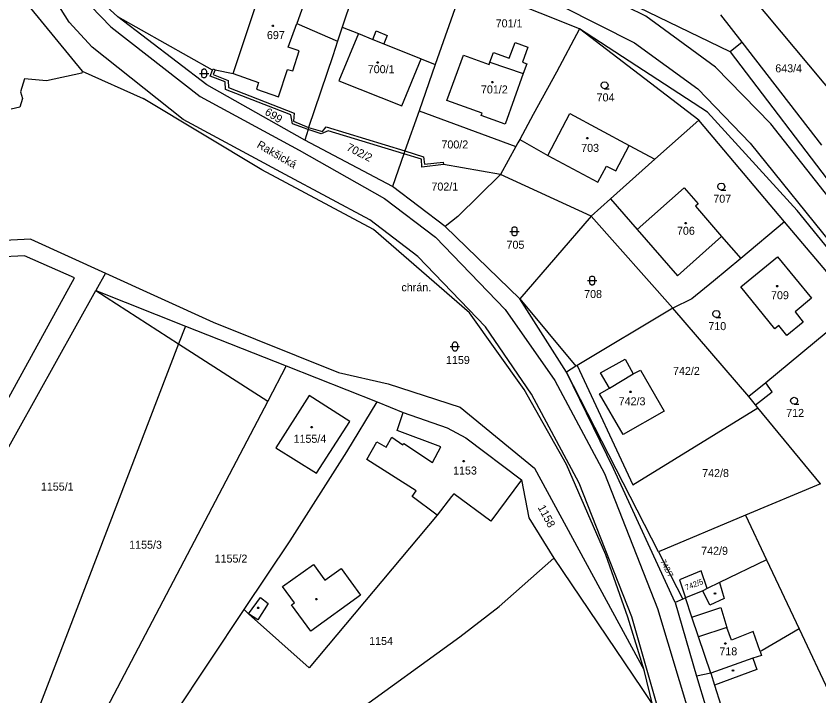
# Model space of a CAD drawing. Extents: x -621797 to -620972, y -1175539 to -1174697.
# Drawn here: x -621483.9 to -621313.4, y -1175130.5 to -1174986.3 of the extents above; entities that cross this region are included whole.
import ezdxf

# ---------------------------------------------------------------- set-up
doc = ezdxf.new("R2010")
doc.units = 0
for name, color, linetype in [('INZ mimo EON - nadz', 7, 'Continuous'), ('Rozvod plynu EON', 7, 'Continuous'), ('SDEL EON', 7, 'Continuous'), ('SDEL EON - popis', 7, 'Continuous'), ('Silnoproud EON', 7, 'Continuous'), ('Silnoproud EON - popis', 7, 'Continuous')]:
    doc.layers.add(name, color=color, linetype=linetype)

msp = doc.modelspace()

# ---------------------------------------------------------------- linework, layer by layer
at = {"layer": 'Rozvod plynu EON'}
for points in [[(-621429.27, -1174988.2), (-621429.18, -1174988.35), (-621429.27, -1174988.5), (-621429.45, -1174988.5), (-621429.54, -1174988.35), (-621429.45, -1174988.2)], [(-621407.03, -1174995.96), (-621406.94, -1174996.11), (-621407.03, -1174996.26), (-621407.21, -1174996.26), (-621407.3, -1174996.11), (-621407.21, -1174995.96)], [(-621382.65, -1175000.18), (-621382.56, -1175000.33), (-621382.65, -1175000.48), (-621382.83, -1175000.48), (-621382.92, -1175000.33), (-621382.83, -1175000.18)], [(-621362.5, -1175012.02), (-621362.41, -1175012.17), (-621362.5, -1175012.32), (-621362.68, -1175012.32), (-621362.77, -1175012.17), (-621362.68, -1175012.02)], [(-621341.64, -1175030.06), (-621341.55, -1175030.21), (-621341.64, -1175030.36), (-621341.82, -1175030.36), (-621341.91, -1175030.21), (-621341.82, -1175030.06)], [(-621322.2, -1175043.44), (-621322.11, -1175043.59), (-621322.2, -1175043.74), (-621322.38, -1175043.74), (-621322.47, -1175043.59), (-621322.38, -1175043.44)], [(-621353.34, -1175065.85), (-621353.25, -1175066), (-621353.34, -1175066.15), (-621353.52, -1175066.15), (-621353.61, -1175066), (-621353.52, -1175065.85)], [(-621421.04, -1175073.36), (-621420.95, -1175073.51), (-621421.04, -1175073.66), (-621421.22, -1175073.66), (-621421.31, -1175073.51), (-621421.22, -1175073.36)], [(-621388.77, -1175080.59), (-621388.68, -1175080.74), (-621388.77, -1175080.89), (-621388.95, -1175080.89), (-621389.04, -1175080.74), (-621388.95, -1175080.59)], [(-621335.38, -1175108.68), (-621335.29, -1175108.83), (-621335.38, -1175108.98), (-621335.56, -1175108.98), (-621335.65, -1175108.83), (-621335.56, -1175108.68)], [(-621420.01, -1175109.87), (-621419.92, -1175110.02), (-621420.01, -1175110.17), (-621420.19, -1175110.17), (-621420.28, -1175110.02), (-621420.19, -1175109.87)], [(-621432.39, -1175111.69), (-621432.3, -1175111.84), (-621432.39, -1175111.99), (-621432.57, -1175111.99), (-621432.66, -1175111.84), (-621432.57, -1175111.69)], [(-621333.19, -1175119.25), (-621333.1, -1175119.4), (-621333.19, -1175119.55), (-621333.37, -1175119.55), (-621333.46, -1175119.4), (-621333.37, -1175119.25)], [(-621331.58, -1175124.97), (-621331.49, -1175125.12), (-621331.58, -1175125.27), (-621331.76, -1175125.27), (-621331.85, -1175125.12), (-621331.76, -1175124.97)]]:
    msp.add_lwpolyline(points, close=True, dxfattribs=at)
at = {"layer": 'SDEL EON'}
for points in [[(-621444.47, -1174997.95), (-621444.37, -1174997.66), (-621444.12, -1174997.48), (-621443.81, -1174997.48), (-621443.56, -1174997.66), (-621443.46, -1174997.95), (-621443.46, -1174998.95), (-621443.56, -1174999.24), (-621443.81, -1174999.42), (-621444.12, -1174999.42), (-621444.37, -1174999.24), (-621444.47, -1174998.95)], [(-621378.56, -1175031.46), (-621378.46, -1175031.17), (-621378.21, -1175030.99), (-621377.9, -1175030.99), (-621377.65, -1175031.17), (-621377.55, -1175031.46), (-621377.55, -1175032.46), (-621377.65, -1175032.75), (-621377.9, -1175032.93), (-621378.21, -1175032.93), (-621378.46, -1175032.75), (-621378.56, -1175032.46)], [(-621362.08, -1175041.91), (-621361.98, -1175041.62), (-621361.73, -1175041.44), (-621361.42, -1175041.44), (-621361.17, -1175041.62), (-621361.07, -1175041.91), (-621361.07, -1175042.91), (-621361.17, -1175043.2), (-621361.42, -1175043.38), (-621361.73, -1175043.38), (-621361.98, -1175043.2), (-621362.08, -1175042.91)], [(-621391.2, -1175055.91), (-621391.1, -1175055.62), (-621390.85, -1175055.44), (-621390.54, -1175055.44), (-621390.29, -1175055.62), (-621390.19, -1175055.91), (-621390.19, -1175056.91), (-621390.29, -1175057.2), (-621390.54, -1175057.38), (-621390.85, -1175057.38), (-621391.1, -1175057.2), (-621391.2, -1175056.91)]]:
    msp.add_lwpolyline(points, close=True, dxfattribs=at)
for points in [[(-621444.97, -1174998.45), (-621443.7, -1174998.45), (-621442.97, -1174998.45)], [(-621358.93, -1175001.69), (-621359.31, -1175001.59), (-621359.58, -1175001.32), (-621359.68, -1175000.95), (-621359.58, -1175000.58), (-621359.31, -1175000.31), (-621358.94, -1175000.21), (-621358.57, -1175000.31), (-621358.3, -1175000.58), (-621358.2, -1175000.96), (-621358.3, -1175001.34), (-621358.57, -1175001.61), (-621358.95, -1175001.71), (-621357.95, -1175001.71)], [(-621334.15, -1175023.19), (-621334.53, -1175023.09), (-621334.8, -1175022.82), (-621334.9, -1175022.45), (-621334.8, -1175022.08), (-621334.53, -1175021.81), (-621334.16, -1175021.71), (-621333.79, -1175021.81), (-621333.52, -1175022.08), (-621333.42, -1175022.46), (-621333.52, -1175022.84), (-621333.79, -1175023.11), (-621334.17, -1175023.21), (-621333.17, -1175023.21)], [(-621379.06, -1175031.96), (-621377.79, -1175031.96), (-621377.06, -1175031.96)], [(-621362.58, -1175042.41), (-621361.31, -1175042.41), (-621360.58, -1175042.41)], [(-621335.21, -1175050.22), (-621335.59, -1175050.12), (-621335.86, -1175049.85), (-621335.96, -1175049.48), (-621335.86, -1175049.11), (-621335.59, -1175048.84), (-621335.22, -1175048.74), (-621334.85, -1175048.84), (-621334.58, -1175049.11), (-621334.48, -1175049.49), (-621334.58, -1175049.87), (-621334.85, -1175050.14), (-621335.23, -1175050.24), (-621334.23, -1175050.24)], [(-621391.7, -1175056.41), (-621390.43, -1175056.41), (-621389.7, -1175056.41)], [(-621318.68, -1175068.64), (-621319.06, -1175068.54), (-621319.33, -1175068.27), (-621319.43, -1175067.9), (-621319.33, -1175067.53), (-621319.06, -1175067.26), (-621318.69, -1175067.16), (-621318.32, -1175067.26), (-621318.05, -1175067.53), (-621317.95, -1175067.91), (-621318.05, -1175068.29), (-621318.32, -1175068.56), (-621318.7, -1175068.66), (-621317.7, -1175068.66)]]:
    msp.add_lwpolyline(points, dxfattribs=at)
at = {"layer": 'SDEL EON - popis'}
for p, q in [((-621350.15, -1174986.32), (-621364.76, -1174979.08)), ((-621472.58, -1174987.57), (-621475.19, -1174983.54)), ((-621468.04, -1174984.21), (-621463.78, -1174988.57)), ((-621368.03, -1174984.17), (-621352.56, -1174991.96)), ((-621467.72, -1174992.88), (-621472.58, -1174987.57)), ((-621426.08, -1174992.85), (-621424.29, -1174987.85)), ((-621335.41, -1174997.12), (-621350.15, -1174986.32)), ((-621463.78, -1174988.57), (-621444.82, -1175003.37)), ((-621411.18, -1174990.01), (-621415.34, -1174999.99)), ((-621408.17, -1174991.22), (-621405.81, -1174992.17)), ((-621448.44, -1175008.26), (-621467.72, -1174992.88)), ((-621423.77, -1174993.68), (-621426.08, -1174992.85)), ((-621352.56, -1174991.96), (-621339.11, -1175001.74)), ((-621425.15, -1174997.93), (-621423.77, -1174993.68)), ((-621402, -1175005.34), (-621397.86, -1174995.37)), ((-621383.26, -1174996.06), (-621376.19, -1174998.49)), ((-621441.59, -1174997.7), (-621442.03, -1174998.7)), ((-621428.16, -1175003.44), (-621426.24, -1174997.59)), ((-621426.24, -1174997.59), (-621425.15, -1174997.93)), ((-621323.62, -1175009.12), (-621335.41, -1174997.12)), ((-621442.03, -1174998.7), (-621438.86, -1174999.94)), ((-621437.78, -1174998.47), (-621432.38, -1175000.41)), ((-621438.86, -1174999.94), (-621438.76, -1175001.46)), ((-621438.76, -1175001.46), (-621424.83, -1175006.86)), ((-621432.38, -1175000.41), (-621432.86, -1175001.82)), ((-621415.34, -1174999.99), (-621402, -1175005.34)), ((-621432.86, -1175001.82), (-621428.16, -1175003.44)), ((-621339.11, -1175001.74), (-621328.01, -1175013.22)), ((-621444.82, -1175003.37), (-621423.78, -1175014.7)), ((-621426.75, -1175019.91), (-621448.44, -1175008.26)), ((-621424.83, -1175006.86), (-621424.97, -1175008.6)), ((-621424.97, -1175008.6), (-621421.81, -1175009.93)), ((-621421.81, -1175009.93), (-621418.81, -1175010.74)), ((-621418.81, -1175010.74), (-621418.01, -1175009.8)), ((-621418.01, -1175009.8), (-621401.31, -1175014.91)), ((-621282.85, -1175060.98), (-621323.62, -1175009.12)), ((-621328.01, -1175013.22), (-621287.02, -1175064.24)), ((-621423.78, -1175014.7), (-621405.63, -1175025)), ((-621401.31, -1175014.91), (-621397.36, -1175016.12)), ((-621356.52, -1175019.14), (-621353.7, -1175013.73)), ((-621397.36, -1175016.12), (-621397.16, -1175017.74)), ((-621370.99, -1175015.9), (-621360.4, -1175021.51)), ((-621397.16, -1175017.74), (-621393.22, -1175017.3)), ((-621393.22, -1175017.3), (-621393.11, -1175017.81)), ((-621360.4, -1175021.51), (-621358.54, -1175018.11)), ((-621358.54, -1175018.11), (-621356.52, -1175019.14)), ((-621408.77, -1175029.49), (-621426.75, -1175019.91)), ((-621405.63, -1175025), (-621394.86, -1175033.18)), ((-621398.61, -1175037.31), (-621408.77, -1175029.49)), ((-621352.01, -1175031.59), (-621343.43, -1175041.38)), ((-621394.86, -1175033.18), (-621380.01, -1175048.54)), ((-621343.43, -1175041.38), (-621334.08, -1175033.04)), ((-621384.23, -1175052.21), (-621398.61, -1175037.31)), ((-621466.98, -1175044.53), (-621449.39, -1175055.82)), ((-621376.96, -1175046.31), (-621365.06, -1175060.59)), ((-621380.01, -1175048.54), (-621369.49, -1175063.63)), ((-621374.45, -1175066.49), (-621384.23, -1175052.21)), ((-621449.39, -1175055.82), (-621430.45, -1175067.98)), ((-621357.86, -1175065.27), (-621352.83, -1175062.22)), ((-621369.49, -1175063.63), (-621358.94, -1175083.35)), ((-621323.34, -1175066.01), (-621324.69, -1175064.07)), ((-621326.9, -1175068.78), (-621323.34, -1175066.01)), ((-621364.3, -1175085.37), (-621374.45, -1175066.49)), ((-621403, -1175074.21), (-621401.72, -1175070.37)), ((-621393.73, -1175077.67), (-621403, -1175074.21)), ((-621405.28, -1175077.74), (-621404.1, -1175075.63)), ((-621404.1, -1175075.63), (-621401.74, -1175077.27)), ((-621409.38, -1175080.36), (-621407.29, -1175076.62)), ((-621407.29, -1175076.62), (-621405.28, -1175077.74)), ((-621401.74, -1175077.27), (-621401.54, -1175077)), ((-621401.54, -1175077), (-621395.46, -1175081.03)), ((-621395.46, -1175081.03), (-621393.73, -1175077.67)), ((-621398.93, -1175087), (-621409.38, -1175080.36)), ((-621358.94, -1175083.35), (-621347.7, -1175112.01)), ((-621353.17, -1175113.73), (-621364.3, -1175085.37)), ((-621399.8, -1175088.22), (-621398.93, -1175087)), ((-621394.5, -1175092.17), (-621399.8, -1175088.22)), ((-621427.31, -1175107.32), (-621420.76, -1175102.68)), ((-621420.76, -1175102.68), (-621418.34, -1175105.98)), ((-621418.34, -1175105.98), (-621414.84, -1175103.48)), ((-621414.84, -1175103.48), (-621410.72, -1175109.19)), ((-621334.51, -1175106.45), (-621333.56, -1175109.87)), ((-621424.78, -1175110.77), (-621427.31, -1175107.32)), ((-621336.62, -1175111.31), (-621338.08, -1175108.26)), ((-621434.56, -1175113.09), (-621431.97, -1175109.65)), ((-621431.97, -1175109.65), (-621430.34, -1175110.95)), ((-621410.72, -1175109.19), (-621421.29, -1175116.83)), ((-621340.39, -1175113.82), (-621341.75, -1175109.71)), ((-621333.56, -1175109.87), (-621336.62, -1175111.31)), ((-621430.34, -1175110.95), (-621432.56, -1175114.38)), ((-621425.37, -1175111.2), (-621424.78, -1175110.77)), ((-621421.29, -1175116.83), (-621425.37, -1175111.2)), ((-621347.7, -1175112.01), (-621340.8, -1175134.9)), ((-621340.39, -1175113.82), (-621334.24, -1175111.78)), ((-621334.24, -1175111.78), (-621332.97, -1175116.04)), ((-621432.56, -1175114.38), (-621434.56, -1175113.09)), ((-621346.63, -1175136.41), (-621353.17, -1175113.73)), ((-621339, -1175118.01), (-621340.39, -1175113.82)), ((-621332.97, -1175116.04), (-621339, -1175118.01)), ((-621331.99, -1175118.72), (-621332.97, -1175116.04)), ((-621327.42, -1175116.9), (-621331.99, -1175118.72)), ((-621325.93, -1175121.13), (-621327.42, -1175116.9)), ((-621336.39, -1175125.7), (-621339, -1175118.01)), ((-621327.46, -1175122.56), (-621326.59, -1175124.96)), ((-621336.39, -1175125.7), (-621335.58, -1175128.26)), ((-621326.59, -1175124.96), (-621335.58, -1175128.26)), ((-621335.58, -1175128.26), (-621334.24, -1175132.49))]:
    msp.add_line(p, q, dxfattribs=at)
at = {"layer": 'Silnoproud EON'}
for p, q in [((-621408.78, -1174971.11), (-621414.62, -1174988.62)), ((-621437.78, -1174998.47), (-621431.19, -1174978.52)), ((-621388.75, -1174979.17), (-621394.87, -1174996.57)), ((-621364.26, -1174989.02), (-621388.75, -1174979.17)), ((-621332.26, -1174993.86), (-621360.13, -1174980.38)), ((-621462.25, -1174986.43), (-621466.27, -1174982.79)), ((-621422.1, -1174981.75), (-621424.29, -1174987.85)), ((-621305.54, -1175008.66), (-621327.66, -1174982.17)), ((-621480.81, -1174984.62), (-621469.86, -1174997.98)), ((-621329.73, -1174991.82), (-621334.24, -1174986.03)), ((-621442.16, -1174997.77), (-621462.25, -1174986.43)), ((-621443.35, -1175000.86), (-621462.25, -1174986.43)), ((-621424.29, -1174987.85), (-621415.61, -1174991.58)), ((-621414.62, -1174988.62), (-621415.61, -1174991.58)), ((-621414.62, -1174988.62), (-621411.18, -1174990.01)), ((-621408.17, -1174991.22), (-621407.46, -1174989.44)), ((-621407.46, -1174989.44), (-621405.09, -1174990.39)), ((-621364.26, -1174989.02), (-621369.14, -1174998.17)), ((-621337.06, -1175006.7), (-621364.26, -1174989.02)), ((-621338.95, -1175008.36), (-621364.26, -1174989.02)), ((-621411.18, -1174990.01), (-621408.17, -1174991.22)), ((-621405.09, -1174990.39), (-621405.81, -1174992.17)), ((-621415.61, -1174991.58), (-621416.66, -1174994.72)), ((-621405.81, -1174992.17), (-621397.86, -1174995.37)), ((-621379.17, -1174995.2), (-621377.95, -1174991.86)), ((-621377.95, -1174991.86), (-621375.23, -1174992.86)), ((-621375.23, -1174992.86), (-621376.38, -1174996.08)), ((-621329.73, -1174991.82), (-621332.26, -1174993.86)), ((-621312.83, -1175013.67), (-621329.73, -1174991.82)), ((-621416.66, -1174994.72), (-621421.81, -1175009.93)), ((-621392.39, -1175004.19), (-621388.92, -1174994.58)), ((-621388.92, -1174994.58), (-621383.45, -1174996.57)), ((-621383.26, -1174996.06), (-621382.5, -1174993.98)), ((-621382.5, -1174993.98), (-621379.17, -1174995.2)), ((-621332.26, -1174993.86), (-621281.81, -1175060.17)), ((-621397.86, -1174995.37), (-621394.87, -1174996.57)), ((-621383.45, -1174996.57), (-621383.26, -1174996.06)), ((-621376.38, -1174996.08), (-621375.44, -1174996.42)), ((-621375.44, -1174996.42), (-621376.19, -1174998.49)), ((-621469.86, -1174997.98), (-621469.95, -1174998.37)), ((-621469.86, -1174997.98), (-621456.9, -1175003.74)), ((-621442.7, -1174999.06), (-621442.16, -1174997.77)), ((-621442.16, -1174997.77), (-621442.05, -1174997.49)), ((-621442.05, -1174997.49), (-621441.59, -1174997.7)), ((-621441.59, -1174997.7), (-621437.78, -1174998.47)), ((-621394.87, -1174996.57), (-621398.31, -1175006.37)), ((-621369.14, -1174998.17), (-621374.08, -1175007.2)), ((-621482.1, -1174999.58), (-621482.97, -1175002.34)), ((-621477.45, -1175000.01), (-621482.1, -1174999.58)), ((-621469.95, -1174998.37), (-621477.45, -1175000.01)), ((-621439.51, -1175000.25), (-621442.7, -1174999.06)), ((-621376.19, -1174998.49), (-621380.06, -1175009.23)), ((-621422.6, -1175012.62), (-621443.35, -1175000.86)), ((-621439.44, -1175001.88), (-621439.51, -1175000.25)), ((-621482.97, -1175002.34), (-621482.49, -1175003.74)), ((-621425.56, -1175007.21), (-621439.44, -1175001.88)), ((-621482.49, -1175003.74), (-621483.1, -1175005.58)), ((-621431.69, -1175018.92), (-621456.9, -1175003.74)), ((-621384.91, -1175006.89), (-621392.39, -1175004.19)), ((-621483.1, -1175005.58), (-621484.9, -1175006.03)), ((-621398.31, -1175006.37), (-621401.31, -1175014.91)), ((-621398.31, -1175006.37), (-621377.79, -1175013.96)), ((-621318.03, -1175027.56), (-621337.06, -1175006.7)), ((-621425.17, -1175009.18), (-621425.56, -1175007.21)), ((-621385.1, -1175007.41), (-621384.91, -1175006.89)), ((-621380.06, -1175009.23), (-621385.1, -1175007.41)), ((-621374.08, -1175007.2), (-621376.96, -1175012.46)), ((-621370.99, -1175015.9), (-621366.3, -1175006.92)), ((-621366.3, -1175006.92), (-621353.7, -1175013.73)), ((-621338.95, -1175008.36), (-621348.26, -1175016.67)), ((-621320.75, -1175029.91), (-621338.95, -1175008.36)), ((-621421.86, -1175010.32), (-621425.17, -1175009.18)), ((-621421.81, -1175009.93), (-621421.86, -1175010.32)), ((-621421.86, -1175010.32), (-621422.6, -1175012.62)), ((-621419.08, -1175011.24), (-621421.86, -1175010.32)), ((-621417.61, -1175010.6), (-621419.08, -1175011.24)), ((-621401.52, -1175015.52), (-621417.61, -1175010.6)), ((-621403.95, -1175022.42), (-621422.6, -1175012.62)), ((-621377.37, -1175013.19), (-621377.79, -1175013.96)), ((-621376.96, -1175012.46), (-621377.37, -1175013.19)), ((-621376.96, -1175012.46), (-621370.99, -1175015.9)), ((-621401.31, -1175014.91), (-621401.52, -1175015.52)), ((-621377.79, -1175013.96), (-621381.06, -1175019.93)), ((-621353.7, -1175013.73), (-621348.26, -1175016.67)), ((-621401.52, -1175015.52), (-621403.95, -1175022.42)), ((-621397.79, -1175016.66), (-621401.52, -1175015.52)), ((-621397.73, -1175018.35), (-621397.79, -1175016.66)), ((-621348.26, -1175016.67), (-621357.7, -1175025.09)), ((-621393.11, -1175017.81), (-621397.73, -1175018.35)), ((-621381.06, -1175019.93), (-621393.11, -1175017.81)), ((-621407.96, -1175031.58), (-621431.69, -1175018.92)), ((-621381.06, -1175019.93), (-621390.1, -1175028.8)), ((-621361.76, -1175028.72), (-621381.06, -1175019.93)), ((-621392.81, -1175030.95), (-621403.95, -1175022.42)), ((-621352.01, -1175031.59), (-621342, -1175022.73)), ((-621342, -1175022.73), (-621339.05, -1175026.11)), ((-621357.7, -1175025.09), (-621361.76, -1175028.72)), ((-621357.7, -1175025.09), (-621352.01, -1175031.59)), ((-621339.05, -1175026.11), (-621339.65, -1175026.63)), ((-621339.65, -1175026.63), (-621334.08, -1175033.04)), ((-621390.1, -1175028.8), (-621392.81, -1175030.95)), ((-621361.76, -1175028.72), (-621376.96, -1175046.31)), ((-621344.47, -1175048.24), (-621361.76, -1175028.72)), ((-621287.81, -1175064.86), (-621318.03, -1175027.56)), ((-621320.75, -1175029.91), (-621330.03, -1175037.69)), ((-621305.4, -1175048.11), (-621320.75, -1175029.91)), ((-621387.58, -1175049.25), (-621407.96, -1175031.58)), ((-621376.96, -1175046.31), (-621392.81, -1175030.95)), ((-621480.74, -1175033.65), (-621493.2, -1175034.17)), ((-621480.74, -1175033.65), (-621464.92, -1175040.83)), ((-621334.08, -1175033.04), (-621330.03, -1175037.69)), ((-621482.07, -1175037.14), (-621492.03, -1175037.67)), ((-621471.46, -1175041.86), (-621482.07, -1175037.14)), ((-621330.01, -1175043.76), (-621322.21, -1175037.35)), ((-621322.21, -1175037.35), (-621315.03, -1175046.12)), ((-621330.03, -1175037.69), (-621335.79, -1175042.51)), ((-621504.52, -1175101.59), (-621471.46, -1175041.86)), ((-621464.92, -1175040.83), (-621466.98, -1175044.53)), ((-621464.92, -1175040.83), (-621442.07, -1175051.21)), ((-621335.79, -1175042.51), (-621340.43, -1175046.29)), ((-621322.77, -1175052.64), (-621330.01, -1175043.76)), ((-621500.4, -1175104.54), (-621466.98, -1175044.53)), ((-621466.98, -1175044.53), (-621447.92, -1175052.07)), ((-621367.02, -1175061.87), (-621376.96, -1175046.31)), ((-621340.43, -1175046.29), (-621344.47, -1175048.24)), ((-621315.03, -1175046.12), (-621318.48, -1175049.04)), ((-621376.02, -1175065.52), (-621387.58, -1175049.25)), ((-621344.47, -1175048.24), (-621364.75, -1175060.41)), ((-621328.32, -1175067.04), (-621344.47, -1175048.24)), ((-621305.4, -1175048.11), (-621324.69, -1175064.07)), ((-621318.48, -1175049.04), (-621316.76, -1175051.21)), ((-621447.92, -1175052.07), (-621449.39, -1175055.82)), ((-621447.92, -1175052.07), (-621426.54, -1175060.52)), ((-621442.07, -1175051.21), (-621415.42, -1175061.9)), ((-621321.94, -1175051.95), (-621322.77, -1175052.64)), ((-621320.22, -1175054.05), (-621321.94, -1175051.95)), ((-621316.76, -1175051.21), (-621320.22, -1175054.05)), ((-621449.39, -1175055.82), (-621480.19, -1175136)), ((-621359.82, -1175062.01), (-621354.53, -1175059.06)), ((-621354.53, -1175059.06), (-621352.83, -1175062.22)), ((-621426.54, -1175060.52), (-621430.45, -1175067.98)), ((-621426.54, -1175060.52), (-621407.22, -1175068.16)), ((-621365.06, -1175060.59), (-621367.02, -1175061.87)), ((-621364.75, -1175060.41), (-621365.06, -1175060.59)), ((-621364.75, -1175060.41), (-621352.91, -1175085.78)), ((-621415.42, -1175061.9), (-621404.88, -1175064.31)), ((-621357.01, -1175082.25), (-621367.02, -1175061.87)), ((-621347.49, -1175099.94), (-621367.02, -1175061.87)), ((-621357.86, -1175065.27), (-621359.82, -1175062.01)), ((-621352.83, -1175062.22), (-621351.28, -1175061.43)), ((-621351.28, -1175061.43), (-621346.27, -1175070.12)), ((-621404.88, -1175064.31), (-621389.62, -1175069.25)), ((-621324.69, -1175064.07), (-621328.32, -1175067.04)), ((-621367.05, -1175081.42), (-621376.02, -1175065.52)), ((-621359.99, -1175066.45), (-621357.86, -1175065.27)), ((-621430.45, -1175067.98), (-621469.21, -1175141.74)), ((-621421.68, -1175066.78), (-621428.72, -1175077.89)), ((-621413, -1175072.28), (-621421.68, -1175066.78)), ((-621355.01, -1175075.1), (-621359.99, -1175066.45)), ((-621326.9, -1175068.78), (-621328.32, -1175067.04)), ((-621413.67, -1175078.75), (-621407.22, -1175068.16)), ((-621407.22, -1175068.16), (-621401.72, -1175070.37)), ((-621389.62, -1175069.25), (-621373.78, -1175082.22)), ((-621352.91, -1175085.78), (-621326.36, -1175069.44)), ((-621326.36, -1175069.44), (-621326.9, -1175068.78)), ((-621313.11, -1175085.57), (-621326.36, -1175069.44)), ((-621401.72, -1175070.37), (-621392.32, -1175073.64)), ((-621346.27, -1175070.12), (-621355.01, -1175075.1)), ((-621420.09, -1175083.3), (-621413, -1175072.28)), ((-621392.32, -1175073.64), (-621388.4, -1175075.81)), ((-621388.4, -1175075.81), (-621376.56, -1175084.7)), ((-621428.72, -1175077.89), (-621420.09, -1175083.3)), ((-621425.71, -1175097.61), (-621413.67, -1175078.75)), ((-621358.7, -1175100.59), (-621367.05, -1175081.42)), ((-621373.78, -1175082.22), (-621350.54, -1175125.06)), ((-621343.93, -1175110.69), (-621357.01, -1175082.25)), ((-621376.56, -1175084.7), (-621383.07, -1175093.49)), ((-621376.56, -1175084.7), (-621375.05, -1175092.73)), ((-621313.11, -1175085.57), (-621328.99, -1175092.21)), ((-621391.42, -1175088.25), (-621394.5, -1175092.17)), ((-621390.96, -1175087.67), (-621391.42, -1175088.25)), ((-621383.07, -1175093.49), (-621390.96, -1175087.67)), ((-621394.5, -1175092.17), (-621421.63, -1175124.56)), ((-621375.05, -1175092.73), (-621369.74, -1175101.33)), ((-621328.99, -1175092.21), (-621347.49, -1175099.94)), ((-621328.99, -1175092.21), (-621324.52, -1175101.66)), ((-621435.42, -1175112.17), (-621425.71, -1175097.61)), ((-621347.49, -1175099.94), (-621342.34, -1175109.98)), ((-621381.34, -1175111.6), (-621369.74, -1175101.33)), ((-621369.74, -1175101.33), (-621351.04, -1175128.93)), ((-621353.99, -1175113.81), (-621358.7, -1175100.59)), ((-621324.52, -1175101.66), (-621334.51, -1175106.45)), ((-621324.52, -1175101.66), (-621317.61, -1175116.28)), ((-621338.41, -1175103.99), (-621343.02, -1175105.92)), ((-621337.14, -1175107.78), (-621338.41, -1175103.99)), ((-621343.02, -1175105.92), (-621341.75, -1175109.71)), ((-621334.51, -1175106.45), (-621337.14, -1175107.78)), ((-621338.08, -1175108.26), (-621341.75, -1175109.71)), ((-621337.14, -1175107.78), (-621338.08, -1175108.26)), ((-621342.34, -1175109.98), (-621343.93, -1175110.69)), ((-621343.93, -1175110.69), (-621339.39, -1175126.33)), ((-621341.75, -1175109.71), (-621342.34, -1175109.98)), ((-621458.77, -1175147.2), (-621435.42, -1175112.17)), ((-621434.56, -1175113.09), (-621435.42, -1175112.17)), ((-621389.63, -1175118.02), (-621381.34, -1175111.6)), ((-621421.63, -1175124.56), (-621434.56, -1175113.09)), ((-621350.54, -1175125.06), (-621353.99, -1175113.81)), ((-621317.61, -1175116.28), (-621325.46, -1175120.92)), ((-621317.61, -1175116.28), (-621310.86, -1175130.56)), ((-621446.08, -1175158.75), (-621389.63, -1175118.02)), ((-621325.46, -1175120.92), (-621325.93, -1175121.13)), ((-621327.46, -1175122.56), (-621336.39, -1175125.7)), ((-621325.65, -1175121.93), (-621327.46, -1175122.56)), ((-621325.93, -1175121.13), (-621325.65, -1175121.93)), ((-621348.77, -1175132.34), (-621350.54, -1175125.06)), ((-621336.39, -1175125.7), (-621339.39, -1175126.33)), ((-621339.39, -1175126.33), (-621337.37, -1175133.15)), ((-621351.04, -1175128.93), (-621348.77, -1175132.34))]:
    msp.add_line(p, q, dxfattribs=at)

# ---------------------------------------------------------------- texts
at = {"layer": 'INZ mimo EON - nadz'}
msp.add_text('Rakšická', height=1.7, rotation=330.13828, dxfattribs=at).set_placement((-621432.914, -1175014.068))
msp.add_text('chrán.', height=1.7, dxfattribs=at).set_placement((-621402.062, -1175044.68))
at = {"layer": 'Silnoproud EON - popis'}
for s, p in [('701/1', (-621382.053, -1174988.68)), ('697', (-621430.623, -1174991.17)), ('643/4', (-621322.693, -1174998.22)), ('700/1', (-621409.213, -1174998.4)), ('701/2', (-621385.183, -1175002.7)), ('704', (-621360.623, -1175004.39)), ('700/2', (-621393.57, -1175014.37)), ('703', (-621363.903, -1175015.1)), ('702/1', (-621395.693, -1175023.31)), ('707', (-621335.843, -1175025.89)), ('706', (-621343.563, -1175032.69)), ('705', (-621379.753, -1175035.66)), ('708', (-621363.273, -1175046.11)), ('709', (-621323.593, -1175046.36)), ('710', (-621336.903, -1175052.92)), ('1159', (-621392.607, -1175060.11)), ('742/2', (-621344.403, -1175062.43)), ('742/3', (-621355.943, -1175068.87)), ('712', (-621320.373, -1175071.34)), ('1155/4', (-621424.97, -1175076.83)), ('1153', (-621391.097, -1175083.56)), ('742/8', (-621338.213, -1175084.1)), ('1155/1', (-621478.617, -1175086.98)), ('1155/3', (-621459.867, -1175099.31)), ('1155/2', (-621441.727, -1175102.25)), ('742/9', (-621338.423, -1175100.59)), ('1154', (-621408.917, -1175119.73)), ('718', (-621334.563, -1175121.93))]:
    msp.add_text(s, height=1.7, dxfattribs=at).set_placement(p)
for s, height, rotation, p in [('699', 1.7, 327.61727, (-621431.229, -1175007.061)), ('702/2', 1.7, 333.00307, (-621413.888, -1175014.678)), ('1158', 1.7, 297.88076, (-621373.166, -1175090.537)), ('742/7', 1.19, 297.19321, (-621347.124, -1175101.968)), ('742/5', 1.19, 20.68378, (-621341.575, -1175108.151))]:
    msp.add_text(s, height=height, rotation=rotation, dxfattribs=at).set_placement(p)

doc.saveas('drawing.dxf')
